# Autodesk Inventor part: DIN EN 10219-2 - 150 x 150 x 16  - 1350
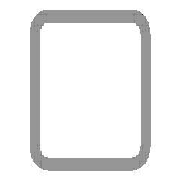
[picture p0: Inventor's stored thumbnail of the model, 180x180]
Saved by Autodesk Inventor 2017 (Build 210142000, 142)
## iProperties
_CCFamilyMember: 76
_CCFamilyDisplayName: DIN EN 10219-2 (Square Hollow Section - Cold Formed) - Cold formed welded structural hollow sections of non-alloy and fine grain structural steel
_FrameMemberDoc: Frame Member File
_Version: 15.0.0
_GetPNFromCC: 1
Created: 2017-11
Part Number: DIN EN 10219-2 - 150 x 150 x 16  - 1350
Material: Steel, Mild
Description: Cold formed welded structural hollow sections of non-alloy and fine grain structural steel
Document SubType Name: Modeling
Standard: DIN
Designer: iusti
Standard Revision: 2006-07
Standards Organization: DIN
Language: en-US
Size Designation: 150 x 150 x 16
Categories: <MemberInstance><Categories><Category DisplayName="Structural Shapes" InternalName="089c4875-fa83-4c05-b084-43b9cc11f5ed" Mnemonic="GRDR"><CategoryParameter Dis
Stock Number: 150 x 150 x 16
Mass: 79240 g
Surface Area: 12767.4 cm^2
Volume: 10094.3 cm^3
Density: 7.85 g/cm^3
Appearance: Semi-Polished
IsCustomPart: 1
G_L: 1350.000 mm
G_W: 150.000 mm
G_H: 150.000 mm
+746405E1-1F2D-47B5-93D3-CB58C56AE875+CUTDETAIL1: Cut
+F08F13D1-F71F-41A8-894A-BF7039D3AEA5+CUTDETAIL2: Cut
+B83B782A-F5FC-4E0E-926C-3EFD3F60499E+CUTDETAIL3: Cut
Author: iusti
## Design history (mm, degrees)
node "Start plane"
node "End plane"
sketch "Sketch"
  geometry: L1 (-75, -27)-(-75, 27); L2 (-27, 75)-(27, 75); L3 (75, 27)-(75, -27); L4 (27, -75)-(-27, -75); L5 (-27, 59)-(27, 59); L6 (59, 27)-(59, -27); L7 (27, -59)-(-27, -59); L8 (-59, -27)-(-59, 27); L9 (0, 118.918)-(0, -118.918) reference; L10 (-118.918, 0)-(118.918, 0) reference; A1 r 48 centre (-27, -27) between (-75, -27) and (-27, -75); A2 r 48 centre (-27, 27) between (-27, 75) and (-75, 27); A3 r 48 centre (27, 27) between (75, 27) and (27, 75); A4 r 48 centre (27, -27) between (27, -75) and (75, -27); A5 r 32 centre (-27, 27) between (-27, 59) and (-59, 27); A6 r 32 centre (27, 27) between (59, 27) and (27, 59); A7 r 32 centre (27, -27) between (27, -59) and (59, -27); A8 r 32 centre (-27, -27) between (-59, -27) and (-27, -59)
  constraints: 16 end point, 16 point on circle, 8 centre point, 8 tangent, 4 parallel, 3 equal radius, 2 perpendicular, 7 other
  dimensions: "d7" = 48 radius of A1 (= G_IR); "d10" = 150 distance between parallel lines of L2 L4 (= G_H); "d11" = 150 distance between parallel lines of L1 L3 (= G_W); "d12" = 16 distance between parallel lines of L3 L6 (= G_T); "d15" = 75 distance between parallel lines of L2 L10 (= 0.5 x d10); "d16" = 75 distance between parallel lines of L9 L3 (= 0.5 x d11)
extrude "Body" new body sketch "Sketch" stored distance "d3" = 1350 (= G_L); taper "d4" = 0 deg
node "Driven Length"
  sketch "Sketch3"
    geometry: L1 (0, 0)-(10, 0) reference
    constraints: 2 end point, 1 horizontal
  workplane "Work Plane3"
  sketch "Sketch4"
    geometry: L1 (-2, 75)-(12, 75) reference; L2 (-2, 1425)-(12, 1425) reference
    dimensions: "d18" = 1350 distance between parallel lines of L1 L2 (derived)
workplane "Work Plane4"
split "Split1"
workplane "Work Plane5"
split "Split2"
workplane "Work Plane6"
split "Split3"
body "Solid1"
other parameters: "G_W" = 150 [user parameter; used in 1 equation term], "G_H" = 150 [user parameter; used in 1 equation term], "G_T" = 16 [user parameter; used in 1 equation term], "G_IR" = 48 [user parameter; used in 1 equation term], "G_L" = 1350 (= d18) [user parameter; used in 1 equation term], "G_OFFSET_START" = -75 [user parameter; used in 1 equation term], "G_OFFSET_END" = -75 [user parameter; used in 1 equation term], "d13" = 75 (= -G_OFFSET_START), "d14" = 1425 (= G_OFFSET_END + B_L), "d17" = 90 deg
